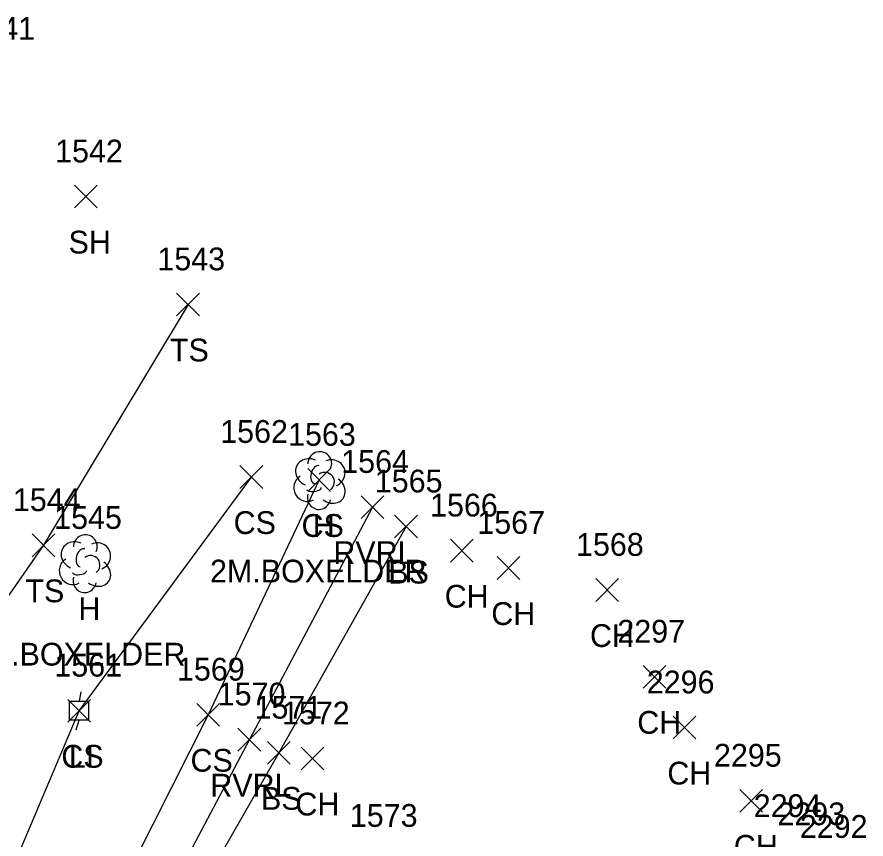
# Model space of a CAD drawing. Extents: x 1504228 to 1506103, y 437717 to 440106.
# Drawn here: x 1505331 to 1505405.6, y 438288.7 to 438360.8 of the extents above; entities that cross this region are included whole.
import ezdxf

# ---------------------------------------------------------------- set-up
doc = ezdxf.new("R2010")
doc.units = 0
for name, color, linetype in [('L_A', 7, 'Continuous'), ('L_C', 7, 'Continuous'), ('L_I', 7, 'Continuous'), ('L_TIC', 7, 'Continuous'), ('LAWE', 7, 'Continuous'), ('LELB', 7, 'Continuous'), ('LTD', 7, 'Continuous'), ('U_A', 7, 'Continuous'), ('U_I', 7, 'Continuous'), ('ULP', 7, 'Continuous')]:
    doc.layers.add(name, color=color, linetype=linetype)

msp = doc.modelspace()

# ---------------------------------------------------------------- linework, layer by layer
at = {"layer": 'L_TIC'}
for points in [[(1505336.015, 438344.071), (1505338.015, 438346.071)], [(1505338.015, 438344.071), (1505336.015, 438346.071)], [(1505344.996, 438334.597), (1505346.996, 438336.597)], [(1505346.996, 438334.597), (1505344.996, 438336.597)], [(1505350.563, 438319.448), (1505352.563, 438321.448)], [(1505352.563, 438319.448), (1505350.563, 438321.448)], [(1505356.525, 438319.193), (1505358.525, 438321.193)], [(1505358.525, 438319.193), (1505356.525, 438321.193)], [(1505361.196, 438316.813), (1505363.196, 438318.813)], [(1505363.196, 438316.813), (1505361.196, 438318.813)], [(1505364.146, 438315.099), (1505366.146, 438317.099)], [(1505366.146, 438315.099), (1505364.146, 438317.099)], [(1505332.305, 438313.456), (1505334.305, 438315.456)], [(1505334.305, 438313.456), (1505332.305, 438315.456)], [(1505369.054, 438312.985), (1505371.054, 438314.985)], [(1505371.054, 438312.985), (1505369.054, 438314.985)], [(1505373.151, 438311.461), (1505375.151, 438313.461)], [(1505375.151, 438311.461), (1505373.151, 438313.461)], [(1505381.821, 438309.531), (1505383.821, 438311.531)], [(1505383.821, 438309.531), (1505381.821, 438311.531)], [(1505385.973, 438301.91), (1505387.973, 438303.91)], [(1505387.973, 438301.91), (1505385.973, 438303.91)], [(1505335.428, 438298.931), (1505337.428, 438300.931)], [(1505337.428, 438298.931), (1505335.428, 438300.931)], [(1505346.775, 438298.58), (1505348.775, 438300.58)], [(1505348.775, 438298.58), (1505346.775, 438300.58)], [(1505388.612, 438297.455), (1505390.612, 438299.455)], [(1505390.612, 438297.455), (1505388.612, 438299.455)], [(1505350.384, 438296.395), (1505352.384, 438298.395)], [(1505352.384, 438296.395), (1505350.384, 438298.395)], [(1505352.966, 438295.236), (1505354.966, 438297.236)], [(1505354.966, 438295.236), (1505352.966, 438297.236)], [(1505355.941, 438294.738), (1505357.941, 438296.738)], [(1505357.941, 438294.738), (1505355.941, 438296.738)], [(1505394.457, 438291.025), (1505396.457, 438293.025)], [(1505396.457, 438291.025), (1505394.457, 438293.025)]]:
    msp.add_lwpolyline(points, dxfattribs=at)
at = {"layer": 'LAWE'}
msp.add_lwpolyline([(1505362.196, 438317.813), (1505351.384, 438297.395), (1505340.369, 438276.571), (1505330.226, 438263.864), (1505321.774, 438253.978), (1505312.194, 438244.278), (1505304.566, 438239.011), (1505294.241, 438232.21), (1505286.327, 438227.151), (1505272.047, 438220.927), (1505261.327, 438215.137), (1505255.057, 438211.857), (1505252.998, 438208.079)], dxfattribs=at)
at = {"layer": 'LELB'}
for points in [[(1505345.996, 438335.597), (1505333.305, 438314.456), (1505321.287, 438297.225), (1505312.638, 438280.068), (1505305.643, 438263.855), (1505289.682, 438249.994), (1505275.731, 438243.689), (1505265.066, 438236.954), (1505253.57, 438228.442), (1505232.624, 438230.462), (1505221.792, 438235.116), (1505209.888, 438231.849), (1505203.313, 438230.133), (1505201.377, 438228.793), (1505195.715, 438225.539), (1505189.868, 438221.089), (1505181.214, 438212.467), (1505175.582, 438209.995), (1505180.422, 438196.297), (1505183.694, 438188.776), (1505173.648, 438207.305)], [(1505270.798, 438231.377), (1505288.172, 438238.832), (1505306.017, 438251.366), (1505315.372, 438266.647), (1505328.992, 438282.411), (1505336.428, 438299.931), (1505351.563, 438320.448)], [(1505357.525, 438320.193), (1505347.775, 438299.58), (1505338.033, 438280.312), (1505328.434, 438265.347), (1505321.109, 438255.57), (1505311.747, 438245.782), (1505304.42, 438239.919), (1505293.736, 438234.076), (1505284.045, 438228.619), (1505270.947, 438221.02), (1505260.492, 438217.948), (1505254.014, 438216.283), (1505247.096, 438215.294)], [(1505365.146, 438316.099), (1505353.966, 438296.236), (1505341.915, 438275.153), (1505332.016, 438262.134), (1505323.954, 438252.628), (1505313.563, 438242.629), (1505305.646, 438236.558), (1505295.746, 438229.78), (1505286.64, 438224.685), (1505273.677, 438216.738), (1505262.485, 438213.279), (1505253.251, 438208.207), (1505250.962, 438202.759), (1505231.919, 438194.06), (1505223.449, 438190.476), (1505215.829, 438187.003), (1505207.689, 438183.331), (1505196.859, 438178.456)]]:
    msp.add_lwpolyline(points, dxfattribs=at)
at = {"layer": 'LTD'}
for p, q in [((1505357.525, 438320.193), (1505357.525, 438320.193)), ((1505357.525, 438320.193), (1505357.525, 438320.193)), ((1505336.93, 438312.898), (1505336.93, 438312.898)), ((1505336.93, 438312.898), (1505336.93, 438312.898))]:
    msp.add_line(p, q, dxfattribs=at)
for centre in [(1505357.572, 438321.627), (1505336.976, 438314.332)]:
    msp.add_arc(centre, 1.047, 335.52715, 180.95627, dxfattribs=at)
for centre, major_axis, ratio, start_param, end_param in [((1505356.733, 438320.86), (1.21, -0.512), 0.895232, 1.570796, 4.712389), ((1505358.567, 438320.777), (-1.141, -0.483), 0.949671, 1.570796, 4.712389), ((1505357.317, 438320.652), (-0.208, -0.792), 0.645439, 3.141593, 6.283185), ((1505356.442, 438319.485), (0.584, -1.042), 0.959034, 3.141593, 6.283185), ((1505358.025, 438320.027), (-0.5, 0.667), 0.989748, 3.141593, 6.283185), ((1505358.525, 438319.36), (-1.09, 0.792), 0.841452, 1.570796, 4.712389), ((1505357.526, 438318.693), (0.265, 1.061), 0.942809, 1.570796, 4.712389), ((1505357.067, 438319.443), (-0.625, -0.083), 0.423636, 0, 3.141593), ((1505336.138, 438313.565), (1.21, -0.512), 0.895232, 1.570796, 4.712389), ((1505337.971, 438313.482), (-1.141, -0.483), 0.949671, 1.570796, 4.712389), ((1505336.721, 438313.357), (-0.208, -0.792), 0.645439, 3.141593, 6.283185), ((1505337.43, 438312.732), (-0.5, 0.667), 0.989748, 3.141593, 6.283185), ((1505335.846, 438312.19), (0.584, -1.042), 0.959034, 3.141593, 6.283185), ((1505337.93, 438312.065), (-1.09, 0.792), 0.841452, 1.570796, 4.712389), ((1505336.471, 438312.148), (-0.625, -0.083), 0.423636, 0, 3.141593), ((1505336.93, 438311.398), (0.265, 1.061), 0.942809, 1.570796, 4.712389)]:
    msp.add_ellipse(centre, major_axis=major_axis, ratio=ratio, start_param=start_param, end_param=end_param, dxfattribs=at)
at = {"layer": 'ULP'}
for p, q in [((1505336.594, 438301.598), (1505336.428, 438300.764)), ((1505335.594, 438299.098), (1505335.594, 438300.764)), ((1505335.594, 438300.764), (1505337.261, 438300.764)), ((1505337.261, 438300.764), (1505337.261, 438299.098)), ((1505336.428, 438299.931), (1505336.428, 438299.931)), ((1505337.261, 438299.098), (1505335.594, 438299.098)), ((1505336.178, 438298.264), (1505336.428, 438299.098))]:
    msp.add_line(p, q, dxfattribs=at)

# ---------------------------------------------------------------- texts
at = {"layer": 'L_A'}
for s, p in [('SH', (1505335.503, 438340.071)), ('TS', (1505344.405, 438330.597)), ('CS', (1505350.004, 438315.448)), ('CS', (1505355.966, 438315.193)), ('H', (1505356.958, 438315.193)), ('RVRL', (1505358.763, 438312.813)), ('BS', (1505363.587, 438311.099)), ('TS', (1505331.715, 438309.456)), ('CH', (1505368.543, 438308.985)), ('H', (1505336.363, 438307.898)), ('CH', (1505372.639, 438307.461)), ('CH', (1505381.309, 438305.531)), ('CH', (1505385.461, 438297.91)), ('CS', (1505334.868, 438294.931)), ('CS', (1505346.216, 438294.58)), ('CH', (1505388.101, 438293.455)), ('RVRL', (1505347.951, 438292.395)), ('BS', (1505352.407, 438291.236)), ('CH', (1505355.43, 438290.738)), ('CH', (1505393.946, 438287.025))]:
    msp.add_text(s, height=2, dxfattribs=at).set_placement(p)
at = {"layer": 'L_C'}
for s, p in [('2M.BOXELDER', (1505347.927, 438311.193)), ('M.BOXELDER', (1505328.229, 438303.898))]:
    msp.add_text(s, height=2, dxfattribs=at).set_placement(p)
at = {"layer": 'L_I'}
for s, p in [('1541', (1505326.611, 438358.838)), ('1542', (1505334.322, 438348.071)), ('1543', (1505343.303, 438338.597)), ('1562', (1505348.823, 438323.448)), ('1563', (1505354.785, 438323.193)), ('1563', (1505354.785, 438323.193)), ('1564', (1505359.456, 438320.813)), ('1565', (1505362.406, 438319.099)), ('1544', (1505330.612, 438317.456)), ('1566', (1505367.259, 438316.985)), ('1545', (1505334.237, 438315.898)), ('1567', (1505371.411, 438315.461)), ('1568', (1505380.081, 438313.531)), ('2297', (1505383.713, 438305.91)), ('1561', (1505334.254, 438302.931)), ('1569', (1505345.027, 438302.58)), ('2296', (1505386.297, 438301.455)), ('1570', (1505348.605, 438300.395)), ('1571', (1505351.84, 438299.236)), ('1572', (1505354.249, 438298.738)), ('2295', (1505392.198, 438295.025)), ('2294', (1505395.691, 438290.599)), ('1573', (1505360.212, 438289.738)), ('2293', (1505397.776, 438289.88)), ('2292', (1505399.741, 438288.772))]:
    msp.add_text(s, height=2, dxfattribs=at).set_placement(p)
at = {"layer": 'U_A'}
msp.add_text('LI', height=2, dxfattribs=at).set_placement((1505335.53, 438294.931))
at = {"layer": 'U_I'}
msp.add_text('1561', height=2, dxfattribs=at).set_placement((1505334.254, 438302.931))

doc.saveas('drawing.dxf')
